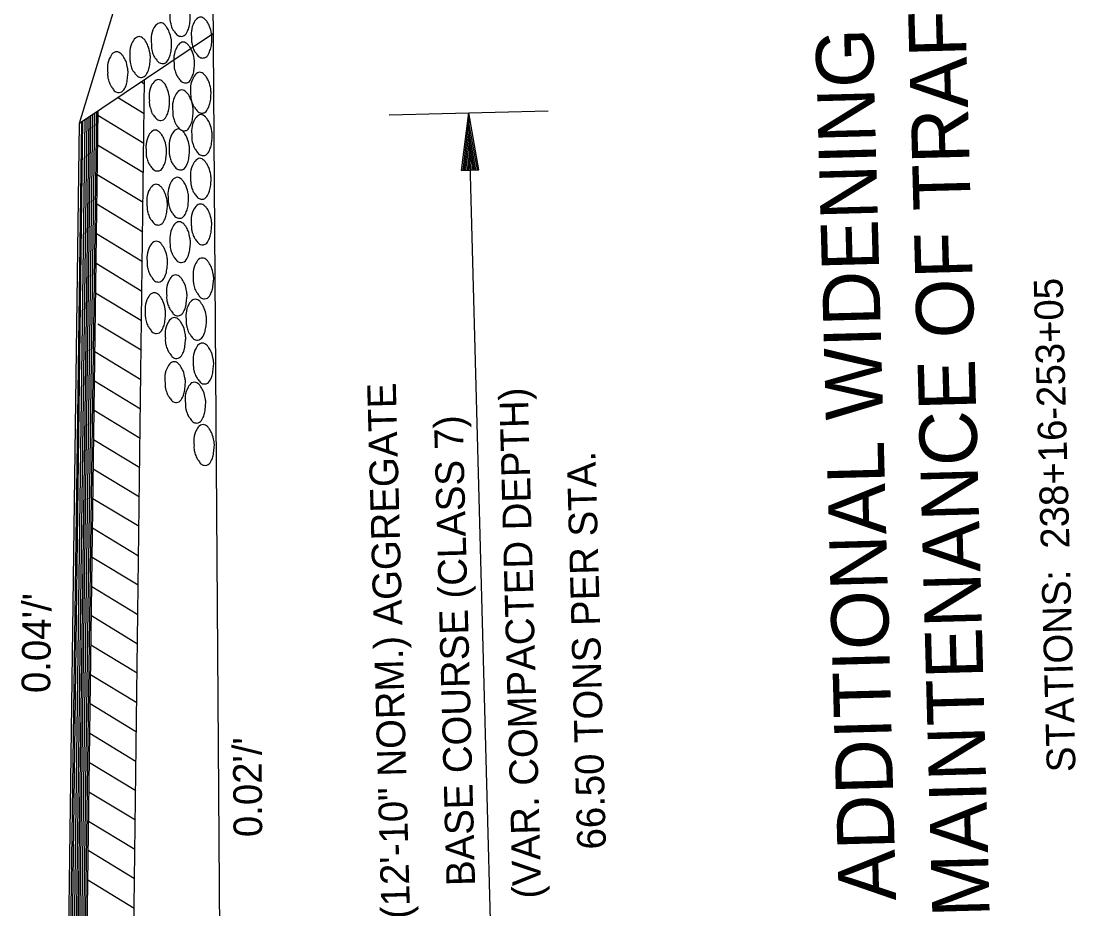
# Model space of a CAD drawing. Extents: x 1926836 to 1933254, y 596317 to 604524.
# Drawn here: x 1933032.9 to 1933253.7, y 596709.2 to 596895 of the extents above; entities that cross this region are included whole.
import ezdxf

# ---------------------------------------------------------------- set-up
doc = ezdxf.new("R2010")
doc.units = 0
doc.layers.add('Default', color=7, linetype='Continuous')

msp = doc.modelspace()

# ---------------------------------------------------------------- linework, layer by layer
at = {"layer": 'Default'}
for p, q in [((1933045.12, 596873.64), (1933105.64, 597072.87)), ((1933075.31, 596577.97), (1933072.67, 596964.34)), ((1933045.12, 596873.64), (1933073.16, 596892.51)), ((1933055.76, 596646.46), (1933058.74, 596882.81)), ((1933058.73, 596881.82), (1933057.97, 596882.29)), ((1933058.65, 596875.63), (1933053.09, 596879.01)), ((1933044.43, 596646.35), (1933047.45, 596875.21)), ((1933044.81, 596646.36), (1933047.89, 596875.5)), ((1933045.23, 596646.38), (1933048.28, 596875.76)), ((1933045.6, 596646.39), (1933048.73, 596876.07)), ((1933045.93, 596646.39), (1933048.99, 596876.24)), ((1933058.57, 596869.43), (1933048.97, 596875.27)), ((1933109.9, 596875.38), (1933143.24, 596876.27)), ((1933125.09, 596863.78), (1933126.57, 596875.82)), ((1933132, 596673.67), (1933126.57, 596875.82)), ((1933128.69, 596863.88), (1933126.57, 596875.82)), ((1933042.08, 596646.29), (1933045.12, 596873.64)), ((1933042.52, 596646.3), (1933045.56, 596873.93)), ((1933042.85, 596646.31), (1933045.83, 596874.12)), ((1933043.27, 596646.32), (1933046.29, 596874.43)), ((1933043.69, 596646.33), (1933046.68, 596874.69)), ((1933044.05, 596646.34), (1933047.13, 596874.99)), ((1933125.39, 596863.79), (1933126.62, 596873.82)), ((1933128.39, 596863.87), (1933126.62, 596873.82)), ((1933125.7, 596863.8), (1933126.68, 596871.75)), ((1933128.08, 596863.86), (1933126.68, 596871.75)), ((1933058.49, 596863.24), (1933048.89, 596869.08)), ((1933126, 596863.8), (1933126.73, 596869.76)), ((1933127.78, 596863.85), (1933126.73, 596869.76)), ((1933126.31, 596863.81), (1933126.79, 596867.73)), ((1933127.48, 596863.84), (1933126.79, 596867.73)), ((1933126.61, 596863.82), (1933126.84, 596865.73)), ((1933127.17, 596863.84), (1933126.84, 596865.73)), ((1933058.42, 596857.04), (1933048.81, 596862.88)), ((1933125.09, 596863.78), (1933128.69, 596863.88)), ((1933058.34, 596850.85), (1933048.73, 596856.69)), ((1933058.26, 596844.65), (1933048.64, 596850.5)), ((1933058.18, 596838.46), (1933048.56, 596844.31)), ((1933058.1, 596832.26), (1933048.48, 596838.11)), ((1933058.03, 596826.13), (1933048.94, 596831.62)), ((1933057.95, 596819.95), (1933048.29, 596825.82)), ((1933057.87, 596813.79), (1933048.22, 596819.67)), ((1933057.79, 596807.66), (1933048.14, 596813.52)), ((1933057.71, 596801.54), (1933048.06, 596807.39)), ((1933057.64, 596795.36), (1933047.99, 596801.21)), ((1933057.56, 596789.24), (1933047.89, 596795.06)), ((1933057.48, 596783.05), (1933047.8, 596788.92)), ((1933057.41, 596776.95), (1933047.76, 596782.78)), ((1933057.33, 596770.76), (1933047.65, 596776.64)), ((1933057.25, 596764.6), (1933047.59, 596770.52)), ((1933057.17, 596758.51), (1933047.5, 596764.38)), ((1933057.1, 596752.34), (1933047.39, 596758.2)), ((1933057.02, 596746.22), (1933047.3, 596752.11)), ((1933056.95, 596740), (1933047.25, 596745.94)), ((1933056.86, 596733.92), (1933047.18, 596739.79)), ((1933056.79, 596727.76), (1933047.08, 596733.65)), ((1933056.71, 596721.6), (1933047.01, 596727.48)), ((1933056.64, 596715.5), (1933046.91, 596721.39)), ((1933056.55, 596709.3), (1933046.82, 596715.21))]:
    msp.add_line(p, q, dxfattribs=at)
for points in [[(1933064.03, 596895.98), (1933064, 596897.45), (1933064.58, 596899.31), (1933065.43, 596900.2), (1933065.93, 596900.38), (1933066.87, 596899.93), (1933067.29, 596899.4), (1933067.8, 596898.43), (1933068.22, 596896.98), (1933068.28, 596896.2), (1933068.25, 596895.11), (1933068.08, 596893.85), (1933067.7, 596892.89), (1933067.02, 596891.98), (1933066.44, 596891.83), (1933065.6, 596892.09), (1933065.02, 596892.76), (1933064.57, 596893.36), (1933064.25, 596894.38), (1933064.07, 596895.02), (1933064.03, 596895.98)], [(1933068.55, 596891.42), (1933068.52, 596892.93), (1933069.11, 596894.77), (1933069.95, 596895.71), (1933070.44, 596895.86), (1933071.38, 596895.39), (1933071.82, 596894.87), (1933072.33, 596893.92), (1933072.74, 596892.42), (1933072.81, 596891.68), (1933072.77, 596890.55), (1933072.58, 596889.33), (1933072.21, 596888.37), (1933071.54, 596887.46), (1933070.92, 596887.3), (1933070.13, 596887.55), (1933069.56, 596888.22), (1933069.1, 596888.86), (1933068.74, 596889.83), (1933068.59, 596890.45), (1933068.55, 596891.42)], [(1933060.14, 596890.28), (1933060.13, 596891.76), (1933060.67, 596893.62), (1933061.51, 596894.51), (1933062.01, 596894.68), (1933062.97, 596894.24), (1933063.38, 596893.71), (1933063.88, 596892.73), (1933064.3, 596891.28), (1933064.38, 596890.5), (1933064.33, 596889.39), (1933064.16, 596888.16), (1933063.78, 596887.2), (1933063.09, 596886.28), (1933062.53, 596886.13), (1933061.7, 596886.38), (1933061.13, 596887.05), (1933060.69, 596887.66), (1933060.31, 596888.68), (1933060.19, 596889.3), (1933060.14, 596890.28)], [(1933055.66, 596887.36), (1933055.64, 596888.87), (1933056.21, 596890.7), (1933057.06, 596891.62), (1933057.56, 596891.79), (1933058.51, 596891.34), (1933058.94, 596890.82), (1933059.42, 596889.84), (1933059.85, 596888.37), (1933059.93, 596887.62), (1933059.88, 596886.49), (1933059.69, 596885.26), (1933059.34, 596884.3), (1933058.65, 596883.4), (1933058.06, 596883.23), (1933057.25, 596883.47), (1933056.65, 596884.15), (1933056.2, 596884.77), (1933055.87, 596885.8), (1933055.71, 596886.41), (1933055.66, 596887.36)], [(1933051, 596884.19), (1933050.97, 596885.72), (1933051.56, 596887.56), (1933052.36, 596888.47), (1933052.9, 596888.61), (1933053.83, 596888.17), (1933054.23, 596887.66), (1933054.78, 596886.68), (1933055.16, 596885.23), (1933055.26, 596884.47), (1933055.18, 596883.36), (1933055, 596882.09), (1933054.66, 596881.13), (1933053.95, 596880.23), (1933053.38, 596880.07), (1933052.55, 596880.31), (1933052, 596880.99), (1933051.57, 596881.62), (1933051.19, 596882.63), (1933051.03, 596883.26), (1933051, 596884.19)], [(1933064.9, 596886.2), (1933064.88, 596887.71), (1933065.47, 596889.54), (1933066.3, 596890.49), (1933066.79, 596890.64), (1933067.75, 596890.16), (1933068.18, 596889.65), (1933068.69, 596888.7), (1933069.11, 596887.2), (1933069.17, 596886.46), (1933069.12, 596885.33), (1933068.94, 596884.1), (1933068.57, 596883.14), (1933067.89, 596882.23), (1933067.27, 596882.08), (1933066.49, 596882.33), (1933065.91, 596882.99), (1933065.46, 596883.64), (1933065.1, 596884.61), (1933064.95, 596885.23), (1933064.9, 596886.2)], [(1933068.37, 596879.88), (1933068.35, 596881.39), (1933068.94, 596883.23), (1933069.78, 596884.17), (1933070.27, 596884.32), (1933071.21, 596883.85), (1933071.65, 596883.33), (1933072.15, 596882.38), (1933072.57, 596880.88), (1933072.63, 596880.15), (1933072.59, 596879.01), (1933072.41, 596877.79), (1933072.04, 596876.83), (1933071.37, 596875.92), (1933070.74, 596875.76), (1933069.96, 596876.01), (1933069.38, 596876.68), (1933068.93, 596877.32), (1933068.57, 596878.3), (1933068.42, 596878.91), (1933068.37, 596879.88)], [(1933059.72, 596878.39), (1933059.7, 596879.87), (1933060.27, 596881.73), (1933061.12, 596882.64), (1933061.63, 596882.8), (1933062.54, 596882.33), (1933063, 596881.81), (1933063.47, 596880.84), (1933063.9, 596879.36), (1933063.97, 596878.61), (1933063.92, 596877.49), (1933063.75, 596876.27), (1933063.39, 596875.31), (1933062.71, 596874.39), (1933062.11, 596874.23), (1933061.3, 596874.49), (1933060.71, 596875.15), (1933060.26, 596875.78), (1933059.94, 596876.79), (1933059.76, 596877.39), (1933059.72, 596878.39)], [(1933064.63, 596876.18), (1933064.6, 596877.69), (1933065.19, 596879.53), (1933066.02, 596880.47), (1933066.52, 596880.62), (1933067.46, 596880.15), (1933067.9, 596879.63), (1933068.4, 596878.68), (1933068.82, 596877.18), (1933068.89, 596876.44), (1933068.84, 596875.31), (1933068.66, 596874.09), (1933068.29, 596873.13), (1933067.62, 596872.22), (1933067, 596872.06), (1933066.21, 596872.31), (1933065.63, 596872.97), (1933065.18, 596873.62), (1933064.82, 596874.59), (1933064.66, 596875.21), (1933064.63, 596876.18)], [(1933068.61, 596871), (1933068.59, 596872.51), (1933069.18, 596874.35), (1933070.01, 596875.29), (1933070.51, 596875.45), (1933071.45, 596874.97), (1933071.89, 596874.45), (1933072.39, 596873.5), (1933072.81, 596872), (1933072.87, 596871.27), (1933072.83, 596870.13), (1933072.65, 596868.91), (1933072.28, 596867.95), (1933071.61, 596867.04), (1933070.98, 596866.89), (1933070.2, 596867.13), (1933069.61, 596867.8), (1933069.17, 596868.44), (1933068.81, 596869.42), (1933068.65, 596870.03), (1933068.61, 596871)], [(1933059.05, 596867.77), (1933059.03, 596869.28), (1933059.62, 596871.12), (1933060.44, 596872.06), (1933060.94, 596872.21), (1933061.89, 596871.74), (1933062.33, 596871.22), (1933062.83, 596870.27), (1933063.24, 596868.77), (1933063.31, 596868.03), (1933063.26, 596866.9), (1933063.09, 596865.68), (1933062.72, 596864.72), (1933062.04, 596863.81), (1933061.42, 596863.65), (1933060.63, 596863.9), (1933060.05, 596864.57), (1933059.6, 596865.21), (1933059.25, 596866.18), (1933059.09, 596866.8), (1933059.05, 596867.77)], [(1933063.88, 596867.99), (1933063.86, 596869.5), (1933064.44, 596871.34), (1933065.27, 596872.28), (1933065.77, 596872.44), (1933066.71, 596871.96), (1933067.16, 596871.44), (1933067.66, 596870.49), (1933068.07, 596868.99), (1933068.14, 596868.26), (1933068.09, 596867.12), (1933067.9, 596865.9), (1933067.54, 596864.93), (1933066.86, 596864.03), (1933066.25, 596863.88), (1933065.46, 596864.12), (1933064.88, 596864.79), (1933064.43, 596865.43), (1933064.08, 596866.4), (1933063.92, 596867.03), (1933063.88, 596867.99)], [(1933068.37, 596861.85), (1933068.35, 596863.37), (1933068.94, 596865.21), (1933069.77, 596866.15), (1933070.26, 596866.31), (1933071.22, 596865.83), (1933071.65, 596865.31), (1933072.16, 596864.36), (1933072.57, 596862.86), (1933072.64, 596862.13), (1933072.59, 596860.99), (1933072.41, 596859.77), (1933072.05, 596858.81), (1933071.36, 596857.9), (1933070.74, 596857.75), (1933069.96, 596857.99), (1933069.38, 596858.66), (1933068.92, 596859.3), (1933068.58, 596860.27), (1933068.42, 596860.9), (1933068.37, 596861.85)], [(1933063.67, 596857.88), (1933063.64, 596859.4), (1933064.23, 596861.23), (1933065.06, 596862.18), (1933065.56, 596862.33), (1933066.5, 596861.85), (1933066.94, 596861.34), (1933067.45, 596860.38), (1933067.86, 596858.88), (1933067.93, 596858.15), (1933067.88, 596857.01), (1933067.7, 596855.79), (1933067.33, 596854.83), (1933066.66, 596853.93), (1933066.04, 596853.77), (1933065.25, 596854.01), (1933064.67, 596854.68), (1933064.22, 596855.32), (1933063.86, 596856.29), (1933063.7, 596856.92), (1933063.67, 596857.88)], [(1933059.23, 596856.46), (1933059.22, 596858), (1933059.79, 596859.84), (1933060.63, 596860.75), (1933061.13, 596860.87), (1933062.09, 596860.43), (1933062.51, 596859.93), (1933063.02, 596858.96), (1933063.42, 596857.49), (1933063.5, 596856.73), (1933063.44, 596855.62), (1933063.25, 596854.39), (1933062.91, 596853.42), (1933062.22, 596852.51), (1933061.63, 596852.34), (1933060.79, 596852.59), (1933060.24, 596853.26), (1933059.78, 596853.9), (1933059.44, 596854.89), (1933059.29, 596855.53), (1933059.23, 596856.46)], [(1933068.51, 596852.32), (1933068.51, 596853.86), (1933069.07, 596855.7), (1933069.91, 596856.61), (1933070.41, 596856.74), (1933071.37, 596856.29), (1933071.8, 596855.79), (1933072.3, 596854.83), (1933072.7, 596853.36), (1933072.78, 596852.59), (1933072.72, 596851.49), (1933072.54, 596850.26), (1933072.19, 596849.28), (1933071.52, 596848.38), (1933070.91, 596848.21), (1933070.07, 596848.45), (1933069.53, 596849.12), (1933069.08, 596849.77), (1933068.72, 596850.75), (1933068.57, 596851.39), (1933068.51, 596852.32)], [(1933064.04, 596848.6), (1933064.05, 596850.14), (1933064.61, 596851.98), (1933065.45, 596852.89), (1933065.95, 596853.02), (1933066.91, 596852.57), (1933067.33, 596852.07), (1933067.84, 596851.11), (1933068.23, 596849.64), (1933068.32, 596848.87), (1933068.25, 596847.77), (1933068.06, 596846.54), (1933067.72, 596845.56), (1933067.04, 596844.66), (1933066.44, 596844.49), (1933065.61, 596844.73), (1933065.06, 596845.4), (1933064.61, 596846.05), (1933064.25, 596847.03), (1933064.11, 596847.66), (1933064.04, 596848.6)], [(1933059.28, 596844.53), (1933059.24, 596846.06), (1933059.84, 596847.9), (1933060.64, 596848.81), (1933061.18, 596848.95), (1933062.11, 596848.51), (1933062.51, 596848), (1933063.06, 596847.02), (1933063.44, 596845.57), (1933063.54, 596844.81), (1933063.46, 596843.7), (1933063.28, 596842.43), (1933062.94, 596841.47), (1933062.23, 596840.57), (1933061.66, 596840.41), (1933060.83, 596840.64), (1933060.28, 596841.33), (1933059.84, 596841.96), (1933059.47, 596842.97), (1933059.31, 596843.59), (1933059.28, 596844.53)], [(1933068.92, 596841.02), (1933068.89, 596842.55), (1933069.48, 596844.39), (1933070.29, 596845.3), (1933070.83, 596845.43), (1933071.76, 596845), (1933072.16, 596844.49), (1933072.71, 596843.5), (1933073.09, 596842.05), (1933073.19, 596841.3), (1933073.11, 596840.18), (1933072.93, 596838.92), (1933072.59, 596837.96), (1933071.88, 596837.06), (1933071.3, 596836.89), (1933070.48, 596837.13), (1933069.93, 596837.82), (1933069.49, 596838.45), (1933069.11, 596839.46), (1933068.96, 596840.08), (1933068.92, 596841.02)], [(1933063.35, 596837.49), (1933063.32, 596839.01), (1933063.91, 596840.85), (1933064.71, 596841.76), (1933065.25, 596841.9), (1933066.18, 596841.46), (1933066.59, 596840.95), (1933067.13, 596839.97), (1933067.51, 596838.52), (1933067.61, 596837.76), (1933067.53, 596836.65), (1933067.36, 596835.38), (1933067.01, 596834.42), (1933066.31, 596833.52), (1933065.73, 596833.36), (1933064.9, 596833.6), (1933064.36, 596834.28), (1933063.92, 596834.91), (1933063.54, 596835.92), (1933063.38, 596836.55), (1933063.35, 596837.49)], [(1933058.87, 596833.75), (1933058.84, 596835.28), (1933059.43, 596837.12), (1933060.24, 596838.03), (1933060.77, 596838.17), (1933061.7, 596837.73), (1933062.11, 596837.22), (1933062.65, 596836.24), (1933063.03, 596834.79), (1933063.13, 596834.03), (1933063.05, 596832.92), (1933062.88, 596831.65), (1933062.53, 596830.69), (1933061.83, 596829.79), (1933061.25, 596829.63), (1933060.43, 596829.86), (1933059.88, 596830.55), (1933059.44, 596831.18), (1933059.06, 596832.19), (1933058.91, 596832.81), (1933058.87, 596833.75)], [(1933067.43, 596832.39), (1933067.4, 596833.92), (1933067.99, 596835.75), (1933068.8, 596836.67), (1933069.34, 596836.8), (1933070.27, 596836.37), (1933070.67, 596835.86), (1933071.22, 596834.87), (1933071.6, 596833.42), (1933071.7, 596832.66), (1933071.62, 596831.55), (1933071.44, 596830.29), (1933071.1, 596829.33), (1933070.39, 596828.43), (1933069.82, 596828.26), (1933068.99, 596828.5), (1933068.44, 596829.18), (1933068, 596829.81), (1933067.63, 596830.82), (1933067.47, 596831.45), (1933067.43, 596832.39)], [(1933063.07, 596828.56), (1933063.04, 596830.09), (1933063.63, 596831.92), (1933064.44, 596832.83), (1933064.97, 596832.97), (1933065.9, 596832.53), (1933066.31, 596832.02), (1933066.85, 596831.04), (1933067.23, 596829.59), (1933067.33, 596828.83), (1933067.25, 596827.72), (1933067.08, 596826.45), (1933066.73, 596825.49), (1933066.03, 596824.59), (1933065.45, 596824.43), (1933064.62, 596824.67), (1933064.08, 596825.35), (1933063.64, 596825.98), (1933063.26, 596826.99), (1933063.1, 596827.62), (1933063.07, 596828.56)], [(1933068.93, 596823.21), (1933068.9, 596824.73), (1933069.49, 596826.57), (1933070.3, 596827.48), (1933070.83, 596827.62), (1933071.77, 596827.18), (1933072.17, 596826.67), (1933072.72, 596825.69), (1933073.09, 596824.24), (1933073.2, 596823.48), (1933073.11, 596822.37), (1933072.94, 596821.1), (1933072.59, 596820.14), (1933071.89, 596819.24), (1933071.31, 596819.08), (1933070.49, 596819.32), (1933069.94, 596820), (1933069.5, 596820.63), (1933069.12, 596821.64), (1933068.97, 596822.27), (1933068.93, 596823.21)], [(1933063.01, 596819.32), (1933062.98, 596820.85), (1933063.57, 596822.69), (1933064.37, 596823.6), (1933064.91, 596823.73), (1933065.84, 596823.3), (1933066.24, 596822.79), (1933066.79, 596821.8), (1933067.17, 596820.35), (1933067.27, 596819.6), (1933067.19, 596818.48), (1933067.01, 596817.22), (1933066.67, 596816.26), (1933065.96, 596815.36), (1933065.39, 596815.19), (1933064.56, 596815.43), (1933064.01, 596816.12), (1933063.58, 596816.75), (1933063.2, 596817.76), (1933063.04, 596818.38), (1933063.01, 596819.32)], [(1933067.27, 596815.03), (1933067.24, 596816.56), (1933067.83, 596818.39), (1933068.64, 596819.31), (1933069.17, 596819.44), (1933070.1, 596819.01), (1933070.51, 596818.5), (1933071.05, 596817.51), (1933071.43, 596816.06), (1933071.53, 596815.3), (1933071.45, 596814.19), (1933071.28, 596812.92), (1933070.93, 596811.96), (1933070.23, 596811.07), (1933069.65, 596810.9), (1933068.82, 596811.14), (1933068.28, 596811.82), (1933067.84, 596812.45), (1933067.46, 596813.46), (1933067.3, 596814.09), (1933067.27, 596815.03)], [(1933069.07, 596806.16), (1933069.04, 596807.69), (1933069.63, 596809.53), (1933070.43, 596810.44), (1933070.97, 596810.58), (1933071.9, 596810.14), (1933072.31, 596809.63), (1933072.85, 596808.65), (1933073.23, 596807.19), (1933073.33, 596806.44), (1933073.25, 596805.32), (1933073.08, 596804.06), (1933072.73, 596803.1), (1933072.03, 596802.2), (1933071.45, 596802.04), (1933070.62, 596802.27), (1933070.07, 596802.96), (1933069.64, 596803.59), (1933069.26, 596804.6), (1933069.1, 596805.22), (1933069.07, 596806.16)]]:
    msp.add_spline(points, degree=3, dxfattribs=at)

# ---------------------------------------------------------------- texts
for s, height, rotation, p in [('FOR MAINTENANCE OF TRAFFIC', 12, 91.5377, (1933236.67, 596669.28)), ('ADDITIONAL WIDENING ', 12, 91.5377, (1933216.04, 596711)), ('STATIONS:  238+16-253+05', 6, 91.5377, (1933253.61, 596737.9)), ('VAR. (12\'-10" NORM.) AGGREGATE', 6, 91.5377, (1933114.88, 596686.23)), ('(VAR. COMPACTED DEPTH)', 6, 91.5377, (1933141.8, 596711.44)), ('BASE COURSE (CLASS 7)', 6, 91.5377, (1933127.93, 596714.07)), ('66.50 TONS PER STA.', 6, 91.5377, (1933155.32, 596721.71)), ("0.04'/'", 6, 89.2454, (1933038.95, 596754.34)), ("0.02'/'", 6, 90.392, (1933083.35, 596724.25))]:
    msp.add_text(s, height=height, rotation=rotation, dxfattribs=at).set_placement(p)

doc.saveas('drawing.dxf')
